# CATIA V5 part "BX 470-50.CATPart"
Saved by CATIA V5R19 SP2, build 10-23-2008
Part number: BX 470-50
Bounding box of the stored display mesh (mm): x -37.351 to 37.351, y -37.351 to 37.351, z 0 to 240
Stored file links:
  C:\Users\Bora\Desktop\3D Katı model\BX serisi\BX 470\BX 470-50.CATPart
  C:\Program Files\Dassault Systemes\B19\intel_a\reffiles\standard\MetricThickPitch.txt
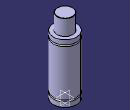
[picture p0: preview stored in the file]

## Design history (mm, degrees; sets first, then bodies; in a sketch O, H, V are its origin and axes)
Body1 (main body)
  Sketch1 on yz-plane, origin (0, 0, 0), H (0, 1, 0), V (0, 0, 1)
    point P1 (37.5, 169.5)
    point P2 (37.5, 174.5)
    arc A1 centre (37.5, 172) radius 2.5 from (37.5, 174.5) to (37.5, 169.5) ccw
    point P3 (37.5, 15.5)
    point P4 (37.5, 20.5)
    arc A2 centre (37.5, 18) radius 2.5 from (37.5, 20.5) to (37.5, 15.5) ccw
    point P5 (37.5, 174.5)
    line L1 (37.5, 189) -> (37.5, 174.5)
    point P8 (25, 239)
    line L2 (25, 239) -> (25, 189)
    point P10 (25, 239)
    arc A3 centre (24, 239) radius 1 from (25, 239) to (24, 240) ccw
    point P11 (37.5, 20.5)
    point P12 (37.5, 169.5)
    line L3 (37.5, 169.5) -> (37.5, 20.5)
    point P14 (37.5, 15.5)
    line L4 (37.5, 15.5) -> (37.5, 0)
    line L5 (24, 240) -> (0, 240)
    point P15 (0, 240)
    line L6 (25, 189) -> (37.5, 189)
    line L7 (37.5, 0) -> (0, 0)
    tangency: L5 A3
    coincidence: P15 V, P1 P12, P2 P5, P3 P14, P4 P11, P8 P10
    horizontal: L6 H, L7 H
  Shaft1: profile Sketch1, axis Sketch1.V, angle 360
  Sketch2 on face of Shaft1 from Sketch1.L7, origin (0, 0, 0), H (1, 0, 0), V (0, -1, 0)
    point P1 (20, 0)
    distance V P1 = 20
  Hole1: placed by Sketch2, at (20, 0, 0) direction (0, 0, 1), diameter 6.647, depth 7, threaded "M8", thread diameter 8, thread depth 7, pitch 1.25
  CircPattern1: of Hole1, instances 4, angular step 90, axis from xy-plane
